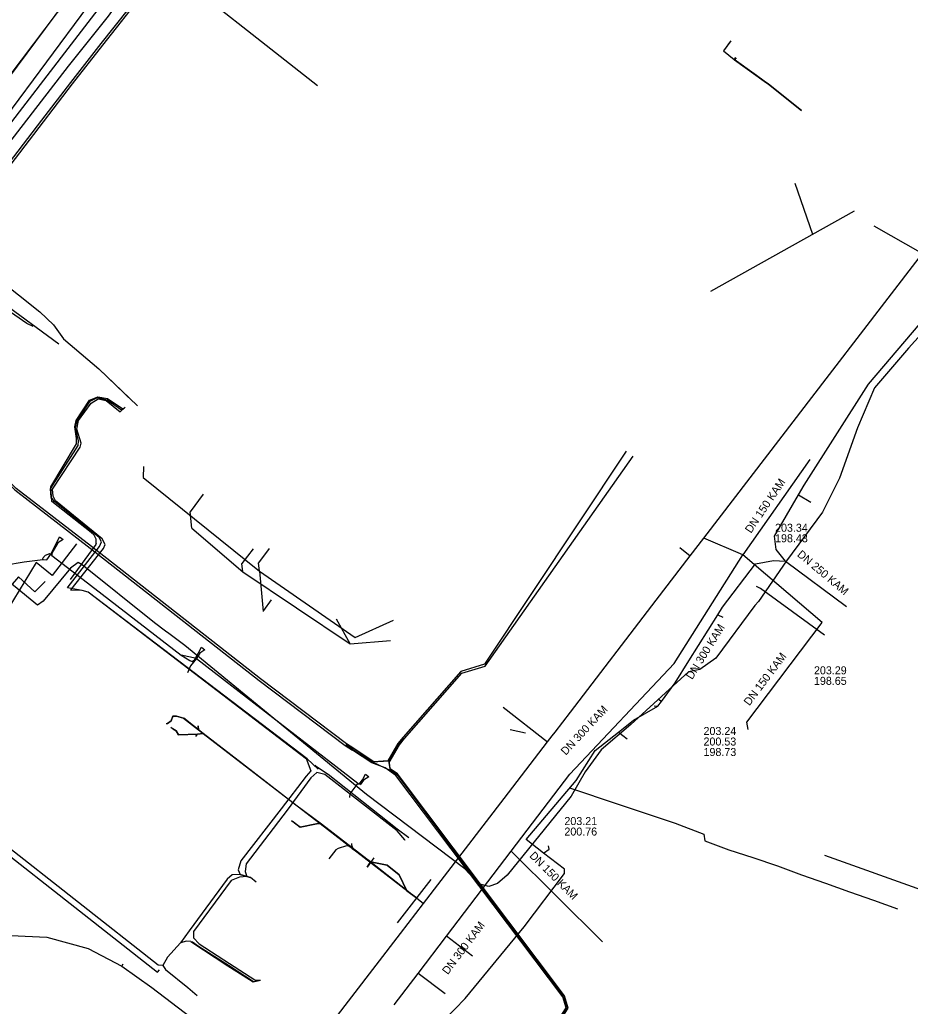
# Model space of a CAD drawing. Extents: x -598932 to -598196, y -1162210 to -1161504.
# Drawn here: x -598784.5 to -598695.5, y -1162123.7 to -1162025.1 of the extents above; entities that cross this region are included whole.
import ezdxf

# ---------------------------------------------------------------- set-up
doc = ezdxf.new("R2010")
doc.units = 0
for name, color, linetype in [('Vrstva 1', 7, 'Continuous'), ('Vrstva 12', 7, 'Continuous'), ('Vrstva 14', 7, 'Continuous'), ('Vrstva 19', 7, 'Continuous'), ('Vrstva 30', 7, 'Continuous'), ('Vrstva 42', 7, 'Continuous'), ('Vrstva 44', 7, 'Continuous'), ('Vrstva 5', 7, 'Continuous'), ('Vrstva 55', 7, 'Continuous'), ('Vrstva 58', 7, 'Continuous'), ('Vrstva 9', 7, 'Continuous')]:
    doc.layers.add(name, color=color, linetype=linetype)

msp = doc.modelspace()

# ---------------------------------------------------------------- linework, layer by layer
at = {"layer": 'Vrstva 1'}
for p, q in [((-598707.05, -1162041.42), (-598705.27, -1162046.54)), ((-598715.44, -1162052.21), (-598701.07, -1162044.19)), ((-598772.15, -1162069.75), (-598772.18, -1162070.84)), ((-598772.18, -1162070.84), (-598760.58, -1162080.2)), ((-598759.582, -1162077.932), (-598760.666, -1162079.378)), ((-598760.58, -1162080.2), (-598760.666, -1162079.378)), ((-598760.58, -1162080.2), (-598760.21, -1162084.25)), ((-598760.14, -1162084.15), (-598759.35, -1162083.08)), ((-598766.65, -1162096.07), (-598766.688, -1162095.688)), ((-598766.19, -1162096.44), (-598766.65, -1162096.07)), ((-598735.5, -1162096.04), (-598733.97, -1162096.38)), ((-598766.94, -1162096.75), (-598766.75, -1162096.51)), ((-598757.21, -1162105.24), (-598756.51, -1162105.8)), ((-598751.31, -1162107.92), (-598750.73, -1162108.34)), ((-598749.14, -1162108.85), (-598749.81, -1162109.8)), ((-598749.14, -1162108.85), (-598749.81, -1162109.8)), ((-598743.43, -1162111.037), (-598746.8, -1162115.356))]:
    msp.add_line(p, q, dxfattribs=at)
for points in [[(-598760.58, -1162080.2), (-598751.01, -1162086.83), (-598747.16, -1162085.12)], [(-598768.15, -1162094.9), (-598768.88, -1162094.71), (-598769.22, -1162094.72), (-598769.41, -1162095.18), (-598769.78, -1162095.43)], [(-598769.78, -1162095.43), (-598769.41, -1162095.18), (-598769.22, -1162094.72), (-598768.88, -1162094.71), (-598768.15, -1162094.9)], [(-598768.15, -1162094.9), (-598766.65, -1162096.07), (-598766.69, -1162095.68)], [(-598744.879, -1162112.887), (-598749.413, -1162109.349), (-598754.376, -1162105.502), (-598756.917, -1162103.613), (-598762.258, -1162099.475), (-598766.191, -1162096.447), (-598768.137, -1162094.901)], [(-598766.19, -1162096.44), (-598766.75, -1162096.51), (-598768.65, -1162096.57), (-598768.91, -1162096.18), (-598769.23, -1162095.96)], [(-598769.23, -1162095.96), (-598768.91, -1162096.18), (-598768.65, -1162096.57), (-598766.75, -1162096.51), (-598766.19, -1162096.44)], [(-598766.19, -1162096.44), (-598756.38, -1162104), (-598754.49, -1162105.44), (-598744.98, -1162112.8), (-598744.86, -1162112.87)], [(-598754.49, -1162105.44), (-598754.88, -1162105.48), (-598756.51, -1162105.8), (-598757.321, -1162105.188)], [(-598756.51, -1162105.8), (-598754.88, -1162105.48), (-598754.49, -1162105.44)], [(-598751.31, -1162107.92), (-598751.59, -1162107.72), (-598751.63, -1162107.7), (-598751.87, -1162107.68), (-598752.71, -1162107.93), (-598752.92, -1162108.06), (-598753.627, -1162108.974)], [(-598751.191, -1162108.006), (-598751.32, -1162107.6), (-598751.34, -1162107.43)], [(-598744.86, -1162112.88), (-598745.82, -1162112.18), (-598746.59, -1162110.56), (-598747.79, -1162109.59), (-598749.47, -1162109.28), (-598750.73, -1162108.34)]]:
    msp.add_lwpolyline(points, dxfattribs=at)
at = {"layer": 'Vrstva 12'}
msp.add_line((-598777.02, -1162019.38), (-598802.51, -1162053.03), dxfattribs=at)
for points in [[(-598754.78, -1162031.71), (-598771.39, -1162018.6), (-598771.58, -1162018.44)], [(-598661.68, -1162036.55), (-598661.15, -1162035.55), (-598660.73, -1162034.67), (-598665.35, -1162032.12), (-598670.72, -1162029.25), (-598671.12, -1162029.18), (-598671.89, -1162029.56), (-598677.12, -1162035.93), (-598679.3, -1162038.79), (-598684.46, -1162045.42), (-598686.07, -1162047.45), (-598691.41, -1162053.08), (-598693.45, -1162055.45), (-598695.67, -1162057.92), (-598699.08, -1162061.9), (-598700.77, -1162065.9), (-598702.58, -1162070.91), (-598704.29, -1162074.31), (-598707.87, -1162079.18), (-598710.67, -1162083.24)], [(-598769.95, -1162086.2), (-598771.06, -1162085.37), (-598778.28, -1162079.57), (-598778.7, -1162079.34), (-598779.47, -1162079.9), (-598782.21, -1162083.21), (-598782.77, -1162083.62), (-598785.16, -1162081.66), (-598791.37, -1162076.97), (-598794.67, -1162074.63)], [(-598710.67, -1162083.24), (-598711.05, -1162083.64), (-598714.95, -1162088.91), (-598716.54, -1162090.04), (-598717.68, -1162090.29), (-598723.45, -1162095.55), (-598726.39, -1162098.06), (-598728.02, -1162100.27), (-598729.41, -1162102.69), (-598735.8, -1162110.59), (-598736.78, -1162111.42), (-598737.63, -1162111.73)], [(-598737.63, -1162111.73), (-598738.62, -1162111.46), (-598740.04, -1162109.97), (-598749.87, -1162102.55), (-598768.02, -1162087.65), (-598769.63, -1162086.44), (-598769.95, -1162086.2)]]:
    msp.add_lwpolyline(points, dxfattribs=at)
at = {"layer": 'Vrstva 14'}
for points in [[(-598792, -1162043.94), (-598779.7, -1162027.98), (-598776.69, -1162024.06)], [(-598801.83, -1162041.89), (-598801.6, -1162042.121), (-598794.632, -1162047.233), (-598780.624, -1162057.499)], [(-598704.078, -1162086.613), (-598710.49, -1162081.95), (-598710.88, -1162081.76)]]:
    msp.add_lwpolyline(points, dxfattribs=at)
at = {"layer": 'Vrstva 19'}
for points in [[(-598730.52, -1161961.88), (-598750.24, -1161987.28), (-598763.31, -1162004.31), (-598765.48, -1162007.14), (-598790.09, -1162040.35)], [(-598778.85, -1162077.48), (-598781.311, -1162080.661), (-598782.906, -1162079.353), (-598787.445, -1162086.795)], [(-598782.01, -1162081.26), (-598783.04, -1162082.28), (-598784.65, -1162080.77), (-598785.48, -1162081.75), (-598789.38, -1162087.36)]]:
    msp.add_lwpolyline(points, dxfattribs=at)
at = {"layer": 'Vrstva 30'}
msp.add_line((-598770.24, -1162119.64), (-598770.68, -1162119.59), dxfattribs=at)
for points in [[(-598779.69, -1162081.79), (-598776.55, -1162077.76), (-598776.37, -1162077.28), (-598776.58, -1162076.85), (-598781.06, -1162073.26), (-598781.4, -1162072.81), (-598781.45, -1162071.99), (-598778.7, -1162067.66), (-598778.67, -1162067.18), (-598778.97, -1162065.88), (-598778.79, -1162065.19), (-598777.48, -1162063.21), (-598776.75, -1162062.85), (-598775.81, -1162063.08), (-598774.37, -1162064.07), (-598774.06, -1162063.88)], [(-598779.38, -1162082.03), (-598776.16, -1162077.96), (-598776, -1162077.56), (-598776.3, -1162076.97), (-598780.95, -1162073.18), (-598781.19, -1162072.72), (-598781.26, -1162072.03), (-598778.48, -1162067.82), (-598778.4, -1162067.43), (-598778.82, -1162066.02), (-598778.65, -1162065.15), (-598777.39, -1162063.41), (-598776.68, -1162062.99), (-598775.88, -1162063.14), (-598774.51, -1162064.28), (-598774.06, -1162063.88)], [(-598778.29, -1162082.15), (-598779.751, -1162081.869), (-598779.69, -1162081.79)], [(-598755.88, -1162099.02), (-598777.68, -1162082.32), (-598778.29, -1162082.15), (-598779.442, -1162082.108), (-598779.38, -1162082.03)], [(-598754.71, -1162100.01), (-598755.8, -1162098.98), (-598777.68, -1162082.32), (-598778.29, -1162082.15)], [(-598755.88, -1162099.02), (-598755.81, -1162099.22), (-598755.44, -1162100.17)], [(-598745.65, -1162106.88), (-598746.79, -1162106), (-598753.7, -1162100.55), (-598754.86, -1162099.77), (-598755, -1162099.59)], [(-598755.44, -1162100.17), (-598755.89, -1162100.7), (-598758.41, -1162103.97), (-598762.44, -1162109.17), (-598762.69, -1162110.07), (-598762.49, -1162110.52), (-598761.84, -1162110.72), (-598761.473, -1162110.848)], [(-598746.01, -1162107.15), (-598746.02, -1162107.07), (-598746.81, -1162106.17), (-598754.03, -1162100.53), (-598754.83, -1162100.32), (-598755.42, -1162100.88), (-598757.79, -1162104.09), (-598761.91, -1162109.45), (-598762, -1162110.24), (-598761.84, -1162110.72)], [(-598770.68, -1162119.59), (-598786.65, -1162107.06), (-598788.06, -1162105.68)], [(-598760.889, -1162111.296), (-598761.473, -1162110.848), (-598761.84, -1162110.72), (-598762.49, -1162110.52), (-598763.3, -1162110.57), (-598763.8, -1162111.01), (-598767.61, -1162116.16), (-598768.46, -1162117.36)], [(-598761.84, -1162110.72), (-598762.56, -1162110.8), (-598763.41, -1162111.13), (-598767.18, -1162116.22), (-598767.15, -1162116.86)], [(-598768.46, -1162117.36), (-598769.75, -1162118.78), (-598770.24, -1162119.64), (-598769.95, -1162120.03), (-598767.73, -1162121.84), (-598766.79, -1162122.63)], [(-598767.431, -1162117.241), (-598767.87, -1162117.19), (-598768.46, -1162117.36)], [(-598767.431, -1162117.241), (-598763.73, -1162119.65), (-598761.2, -1162121.27), (-598760.47, -1162121.11)], [(-598767.431, -1162117.241), (-598767.27, -1162117.26), (-598766.65, -1162117.69), (-598763.68, -1162119.6), (-598761.17, -1162121.23), (-598760.47, -1162121.11)], [(-598767.27, -1162117.26), (-598766.68, -1162117.73), (-598763.73, -1162119.65), (-598761.2, -1162121.27), (-598760.47, -1162121.11)], [(-598767.15, -1162116.86), (-598766.6, -1162117.47), (-598763.57, -1162119.44), (-598761.02, -1162121.06), (-598760.47, -1162121.11)]]:
    msp.add_lwpolyline(points, dxfattribs=at)
at = {"layer": 'Vrstva 42'}
for p, q in [((-598713.462, -1162027.244), (-598714.157, -1162028.216)), ((-598714.157, -1162028.216), (-598713.092, -1162029.076)), ((-598713.092, -1162029.076), (-598712.935, -1162028.881)), ((-598774.009, -1162063.815), (-598774.06, -1162063.88)), ((-598746.65, -1162097.51), (-598746.13, -1162096.87)), ((-598751.93, -1162097.54), (-598751.21, -1162098.03)), ((-598751.21, -1162098.03), (-598749.29, -1162099.27)), ((-598747.61, -1162099.18), (-598746.65, -1162097.51)), ((-598749.29, -1162099.27), (-598747.61, -1162099.18)), ((-598749.29, -1162099.27), (-598747.47, -1162100.12)), ((-598747.47, -1162100.12), (-598747.61, -1162099.18)), ((-598770.748, -1162120.288), (-598770.566, -1162120.055))]:
    msp.add_line(p, q, dxfattribs=at)
for points in [[(-598792.625, -1162046.649), (-598788.371, -1162040.953), (-598779.647, -1162029.747), (-598775.668, -1162024.727), (-598774.132, -1162022.573), (-598769.808, -1162017.21), (-598766.424, -1162012.672), (-598765, -1162010.88), (-598762.903, -1162008.204)], [(-598713.444, -1162027.218), (-598714.157, -1162028.216), (-598713.11, -1162029.06), (-598712.954, -1162028.873)], [(-598710.099, -1162031.219), (-598710.866, -1162030.672), (-598713.092, -1162029.076)], [(-598712.908, -1162028.909), (-598713.057, -1162029.103), (-598710.099, -1162031.219)], [(-598706.36, -1162034.177), (-598709.661, -1162031.545), (-598710.099, -1162031.219)], [(-598710.099, -1162031.219), (-598709.661, -1162031.545), (-598706.36, -1162034.177)], [(-598792.625, -1162046.649), (-598791.249, -1162047.355), (-598782.533, -1162054.305), (-598781.166, -1162055.581), (-598780.157, -1162056.984), (-598776.614, -1162059.971), (-598773.186, -1162063.274)], [(-598783.2, -1162055.76), (-598783.83, -1162055.47), (-598792.74, -1162049.3), (-598793.17, -1162049.03), (-598793.72, -1162049.23), (-598798.22, -1162055.35), (-598798.48, -1162056.38), (-598797.99, -1162058.91), (-598797.16, -1162060.99), (-598794.13, -1162064.26)], [(-598783.2, -1162055.76), (-598783.83, -1162055.47), (-598792.74, -1162049.3), (-598793.17, -1162049.03), (-598793.72, -1162049.23), (-598798.22, -1162055.35), (-598798.48, -1162056.38), (-598797.99, -1162058.91), (-598797.16, -1162060.99), (-598794.13, -1162064.26)], [(-598777.399, -1162076.36), (-598781.33, -1162073.24), (-598781.44, -1162071.79), (-598778.86, -1162067.48), (-598778.85, -1162066.95), (-598779.04, -1162065.8), (-598778.9, -1162065.16), (-598777.57, -1162063.13), (-598776.72, -1162062.8), (-598775.76, -1162062.95), (-598774.24, -1162063.98), (-598774.06, -1162063.88)], [(-598776.9, -1162077.44), (-598776.9, -1162077), (-598777.1, -1162076.61), (-598777.4, -1162076.36)], [(-598776.9, -1162077.44), (-598776.94, -1162077.56), (-598779.506, -1162081.038)], [(-598747.47, -1162100.12), (-598746.85, -1162100.55), (-598730.16, -1162122.72), (-598729.81, -1162123.89), (-598739.6, -1162139.04), (-598748.77, -1162150.8), (-598749.27, -1162153.71), (-598748.78, -1162156.21), (-598730.76, -1162163.16), (-598713.05, -1162169.34), (-598711.55, -1162168.95), (-598709.81, -1162166.32)], [(-598787.013, -1162107.527), (-598779.028, -1162113.792), (-598770.748, -1162120.288)], [(-598787.013, -1162107.527), (-598779.028, -1162113.792), (-598770.748, -1162120.288)]]:
    msp.add_lwpolyline(points, dxfattribs=at)
at = {"layer": 'Vrstva 44'}
for points in [[(-598773.69, -1162024.03), (-598776.427, -1162027.485), (-598779.448, -1162031.357), (-598782.348, -1162035.138), (-598785.168, -1162038.798), (-598788.268, -1162042.848), (-598791.108, -1162046.518), (-598794.247, -1162050.636), (-598796.287, -1162053.406)], [(-598796.133, -1162053.534), (-598794.05, -1162050.79), (-598790.91, -1162046.67), (-598788.07, -1162043), (-598784.97, -1162038.95), (-598782.15, -1162035.29), (-598779.25, -1162031.51), (-598776.23, -1162027.64), (-598773.49, -1162024.18)], [(-598796.287, -1162053.406), (-598797.948, -1162055.409), (-598798.313, -1162056.368), (-598797.895, -1162059.355), (-598796.311, -1162061.04), (-598785.026, -1162072.086), (-598777.481, -1162077.929), (-598760.601, -1162091.139), (-598751.986, -1162097.623), (-598751.274, -1162098.107)], [(-598723.913, -1162068.232), (-598738.069, -1162089.524), (-598740.448, -1162090.233), (-598746.208, -1162096.807), (-598746.733, -1162097.453), (-598747.729, -1162099.186), (-598749.12, -1162099.261), (-598751.146, -1162097.953), (-598751.874, -1162097.457), (-598760.479, -1162090.981), (-598777.363, -1162077.76), (-598784.894, -1162071.934), (-598796.169, -1162060.9), (-598797.705, -1162059.265), (-598798.107, -1162056.392), (-598797.772, -1162055.511), (-598796.84, -1162054.4), (-598796.133, -1162053.534)], [(-598746.567, -1162097.567), (-598746.052, -1162096.933), (-598740.332, -1162090.407), (-598738.011, -1162089.716), (-598723.203, -1162068.731)], [(-598709.713, -1162166.354), (-598711.488, -1162169.037), (-598713.054, -1162169.444), (-598730.794, -1162163.254), (-598748.868, -1162156.283), (-598749.372, -1162153.711), (-598748.864, -1162150.758), (-598739.682, -1162138.982), (-598729.919, -1162123.874), (-598730.251, -1162122.766), (-598746.92, -1162100.623), (-598748.006, -1162099.869), (-598749.344, -1162099.354), (-598751.274, -1162098.107)], [(-598709.907, -1162166.286), (-598711.612, -1162168.863), (-598713.046, -1162169.236), (-598730.726, -1162163.066), (-598748.692, -1162156.137), (-598749.168, -1162153.709), (-598748.676, -1162150.842), (-598739.518, -1162139.098), (-598729.701, -1162123.906), (-598730.069, -1162122.674), (-598746.78, -1162100.477), (-598747.49, -1162099.984), (-598747.586, -1162099.34), (-598746.567, -1162097.567)]]:
    msp.add_lwpolyline(points, dxfattribs=at)
at = {"layer": 'Vrstva 5'}
for p, q in [((-598766.197, -1162072.526), (-598767.501, -1162074.265)), ((-598767.33, -1162075.9), (-598767.501, -1162074.265)), ((-598767.33, -1162075.9), (-598762.23, -1162080.28)), ((-598761.209, -1162077.982), (-598762.316, -1162079.458)), ((-598762.23, -1162080.28), (-598762.316, -1162079.458)), ((-598751.5, -1162087.49), (-598752.87, -1162085.01))]:
    msp.add_line(p, q, dxfattribs=at)
msp.add_lwpolyline([(-598762.23, -1162080.28), (-598751.5, -1162087.49), (-598747.46, -1162087.13)], dxfattribs=at)
at = {"layer": 'Vrstva 55'}
for p, q in [((-598706.66, -1162072.58), (-598705.45, -1162073.3)), ((-598707.97, -1162079.21), (-598701.89, -1162083.74)), ((-598717.65, -1162089.16), (-598714.75, -1162084.58)), ((-598714.75, -1162084.58), (-598714.25, -1162084.81)), ((-598766.85, -1162088.93), (-598768.39, -1162088.61)), ((-598720.63, -1162092.99), (-598720.36, -1162093.23)), ((-598721.11, -1162093.66), (-598720.73, -1162093.72)), ((-598720.73, -1162093.72), (-598720.36, -1162093.23)), ((-598724.67, -1162096.31), (-598723.79, -1162096.96)), ((-598732.17, -1162108.4), (-598733.91, -1162107.04)), ((-598774.34, -1162119.71), (-598774.21, -1162119.46))]:
    msp.add_line(p, q, dxfattribs=at)
for points in [[(-598706.66, -1162072.58), (-598706.1, -1162071.61), (-598699.69, -1162061.51), (-598691.66, -1162052.1)], [(-598707.97, -1162079.21), (-598708.92, -1162078.03), (-598709.06, -1162076.71), (-598706.66, -1162072.58)], [(-598790.02, -1162080.28), (-598784.08, -1162079.29), (-598782.23, -1162079.04), (-598781.83, -1162079.07), (-598781.42, -1162078.52), (-598780.82, -1162077.34), (-598780.55, -1162076.79), (-598780.34, -1162076.95), (-598780.21, -1162077.06), (-598780.72, -1162077.37), (-598781.33, -1162078.42), (-598781.33, -1162078.64), (-598778.2, -1162081.052), (-598768.39, -1162088.61), (-598767.52, -1162089.15), (-598767.31, -1162089.24), (-598767.08, -1162089.08), (-598766.67, -1162088.38), (-598766.38, -1162087.82), (-598766.02, -1162088.09), (-598766.54, -1162088.41), (-598766.85, -1162088.93), (-598763.318, -1162091.66), (-598750.72, -1162101.4), (-598750.594, -1162101.501), (-598750.28, -1162101.06), (-598749.98, -1162100.49), (-598749.843, -1162100.61)], [(-598781.33, -1162078.64), (-598781.55, -1162078.47), (-598781.99, -1162078.66), (-598782.26, -1162078.93), (-598782.23, -1162079.04)], [(-598714.75, -1162084.58), (-598714.28, -1162083.81), (-598710.99, -1162079.47), (-598709.17, -1162079.15), (-598707.97, -1162079.21)], [(-598766.85, -1162088.93), (-598767.45, -1162089.68), (-598767.78, -1162090.37)], [(-598720.36, -1162093.23), (-598719.02, -1162091.39), (-598717.65, -1162089.16)], [(-598724.67, -1162096.31), (-598723.16, -1162095.11), (-598720.73, -1162093.72)], [(-598733.91, -1162107.04), (-598728.92, -1162101.13), (-598726.99, -1162098.13), (-598724.67, -1162096.31)], [(-598749.98, -1162100.49), (-598749.84, -1162100.59), (-598749.65, -1162100.78), (-598750.18, -1162101.1), (-598750.503, -1162101.573)], [(-598750.72, -1162101.4), (-598751.52, -1162102.46), (-598751.58, -1162102.84)], [(-598729.57, -1162101.87), (-598724.71, -1162103.49), (-598719.01, -1162105.39), (-598716.14, -1162106.5), (-598716.03, -1162107.17), (-598713.64, -1162108.05), (-598711.23, -1162108.84), (-598708.79, -1162109.67), (-598706.39, -1162110.56), (-598703.99, -1162111.4), (-598701.57, -1162112.26), (-598699.16, -1162113.09), (-598696.77, -1162113.96)], [(-598732.17, -1162108.4), (-598731.62, -1162108.004), (-598731.66, -1162107.65)], [(-598774.34, -1162119.71), (-598771.33, -1162121.84), (-598763.47, -1162127.84), (-598759.78, -1162129.96), (-598759.65, -1162129.79), (-598759.7, -1162130), (-598757.22, -1162131.13), (-598754.68, -1162131.66), (-598751.07, -1162130.96), (-598745.76, -1162127.9), (-598743.18, -1162126.18), (-598743.23, -1162126.03), (-598743.09, -1162126.11), (-598740, -1162122.94), (-598734.1, -1162115.77), (-598730.07, -1162110.44), (-598730.06, -1162110.01), (-598732.17, -1162108.4)], [(-598704.08, -1162108.61), (-598693.9, -1162112.24), (-598683.26, -1162116.04), (-598682.95, -1162115.03)], [(-598792.99, -1162112.8), (-598792.96, -1162112.89), (-598790.26, -1162115.24), (-598787.99, -1162116.32), (-598785.44, -1162116.64), (-598781.84, -1162116.78), (-598777.68, -1162117.92), (-598774.34, -1162119.71)]]:
    msp.add_lwpolyline(points, dxfattribs=at)
at = {"layer": 'Vrstva 58'}
for points in [[(-598468.847, -1161997.004), (-598474.74, -1161995.919), (-598475.488, -1161995.781), (-598478.287, -1161995.178), (-598494.053, -1161991.976), (-598541.472, -1161981.52), (-598578.948, -1161964.943), (-598630.191, -1161928.985), (-598655.175, -1161905.777), (-598662.179, -1161910.88), (-598682.84, -1161933.505), (-598697.858, -1161918.482), (-598699.937, -1161917.16), (-598721.671, -1161944.79), (-598806.154, -1162058.425), (-598849.895, -1162115.36), (-598896.973, -1162178.006), (-598919.37, -1162206.96)], [(-598792.625, -1162046.649), (-598788.371, -1162040.953), (-598779.647, -1162029.747), (-598775.668, -1162024.727), (-598774.132, -1162022.573), (-598769.808, -1162017.21), (-598766.424, -1162012.672), (-598765, -1162010.88), (-598762.952, -1162008.22)], [(-598792.625, -1162046.649), (-598791.249, -1162047.355), (-598782.533, -1162054.305), (-598781.166, -1162055.581), (-598780.157, -1162056.984), (-598776.614, -1162059.971), (-598772.76, -1162063.685)]]:
    msp.add_lwpolyline(points, dxfattribs=at)
at = {"layer": 'Vrstva 9'}
for p, q in [((-598699.155, -1162045.681), (-598694.293, -1162048.474)), ((-598716.123, -1162076.901), (-598706.882, -1162064.868)), ((-598705.542, -1162069.061), (-598712.248, -1162078.595)), ((-598712.248, -1162078.595), (-598716.123, -1162076.901)), ((-598718.553, -1162077.854), (-598717.492, -1162078.684)), ((-598719.118, -1162089.439), (-598712.248, -1162078.595)), ((-598704.3, -1162085.34), (-598712.248, -1162078.595)), ((-598729.54, -1162100.508), (-598719.118, -1162089.439)), ((-598736.202, -1162093.805), (-598731.764, -1162097.277)), ((-598766.69, -1162095.68), (-598766.65, -1162096.07)), ((-598766.94, -1162096.75), (-598766.75, -1162096.51)), ((-598752.71, -1162107.93), (-598752.92, -1162108.06)), ((-598751.87, -1162107.68), (-598752.71, -1162107.93)), ((-598751.63, -1162107.7), (-598751.87, -1162107.68)), ((-598751.59, -1162107.72), (-598751.63, -1162107.7)), ((-598751.31, -1162107.92), (-598751.59, -1162107.72)), ((-598751.32, -1162107.6), (-598751.34, -1162107.43)), ((-598751.191, -1162108.006), (-598751.32, -1162107.6)), ((-598750.73, -1162108.34), (-598751.31, -1162107.92)), ((-598752.92, -1162108.06), (-598753.627, -1162108.974)), ((-598726.27, -1162117.27), (-598735.39, -1162108.186)), ((-598749.807, -1162109.795), (-598749.47, -1162109.28)), ((-598739.262, -1162118.702), (-598741.872, -1162116.711)), ((-598742.007, -1162122.47), (-598744.697, -1162120.418))]:
    msp.add_line(p, q, dxfattribs=at)
for points in [[(-598706.882, -1162064.868), (-598705.664, -1162063.282), (-598698.051, -1162053.368), (-598694.293, -1162048.474)], [(-598746.471, -1162116.422), (-598744.169, -1162113.418), (-598736.117, -1162102.938), (-598731.764, -1162097.277), (-598731.309, -1162096.685), (-598731.01, -1162096.297), (-598729.482, -1162094.31), (-598720.891, -1162083.11), (-598717.492, -1162078.684), (-598716.123, -1162076.901)], [(-598711.708, -1162096.023), (-598711.844, -1162095.303), (-598704.3, -1162085.34)], [(-598769.89, -1162095.44), (-598769.78, -1162095.43), (-598769.41, -1162095.18), (-598769.22, -1162094.72), (-598768.88, -1162094.71), (-598768.15, -1162094.9), (-598766.65, -1162096.07), (-598766.19, -1162096.44), (-598754.49, -1162105.44), (-598750.73, -1162108.34)], [(-598769.42, -1162095.81), (-598768.91, -1162096.18), (-598768.65, -1162096.57), (-598766.75, -1162096.51), (-598766.19, -1162096.44)], [(-598747.093, -1162123.566), (-598744.697, -1162120.418), (-598741.872, -1162116.711), (-598735.39, -1162108.186), (-598729.54, -1162100.508)], [(-598757.36, -1162105.14), (-598756.51, -1162105.8), (-598754.88, -1162105.48), (-598754.49, -1162105.44)], [(-598757.36, -1162105.14), (-598756.51, -1162105.8), (-598754.88, -1162105.48), (-598754.49, -1162105.44)], [(-598750.73, -1162108.34), (-598749.47, -1162109.28), (-598747.79, -1162109.59), (-598746.59, -1162110.56), (-598745.82, -1162112.18), (-598744.86, -1162112.88), (-598744.169, -1162113.418)], [(-598786.41, -1162168.23), (-598785.816, -1162167.658), (-598781.796, -1162162.423), (-598766.552, -1162142.572), (-598751.343, -1162122.767), (-598746.471, -1162116.422)]]:
    msp.add_lwpolyline(points, dxfattribs=at)

# ---------------------------------------------------------------- texts
at = {"layer": 'Vrstva 12'}
for s, rotation, p in [('DN 150 KAM', 56, (-598711.425, -1162076.48)), ('DN 250 KAM', 320, (-598706.87, -1162078.652)), ('DN 300 KAM', 58, (-598717.309, -1162091.108)), ('DN 150 KAM', 53, (-598711.58, -1162093.724)), ('DN 300 KAM', 47, (-598729.942, -1162098.665)), ('DN 150 KAM', 315, (-598733.641, -1162108.716)), ('DN 300 KAM', 53, (-598741.739, -1162120.597))]:
    msp.add_text(s, height=0.8, rotation=rotation, dxfattribs=at).set_placement(p)
for s, p in [('203.34', (-598709.016, -1162076.272)), ('198.43', (-598709.016, -1162077.322)), ('203.29', (-598705.128, -1162090.525)), ('198.65', (-598705.128, -1162091.575)), ('203.24', (-598716.17, -1162096.589)), ('200.53', (-598716.17, -1162097.639)), ('198.73', (-598716.17, -1162098.689)), ('203.21', (-598730.08, -1162105.589)), ('200.76', (-598730.08, -1162106.639))]:
    msp.add_text(s, height=0.8, dxfattribs=at).set_placement(p)

doc.saveas('drawing.dxf')
